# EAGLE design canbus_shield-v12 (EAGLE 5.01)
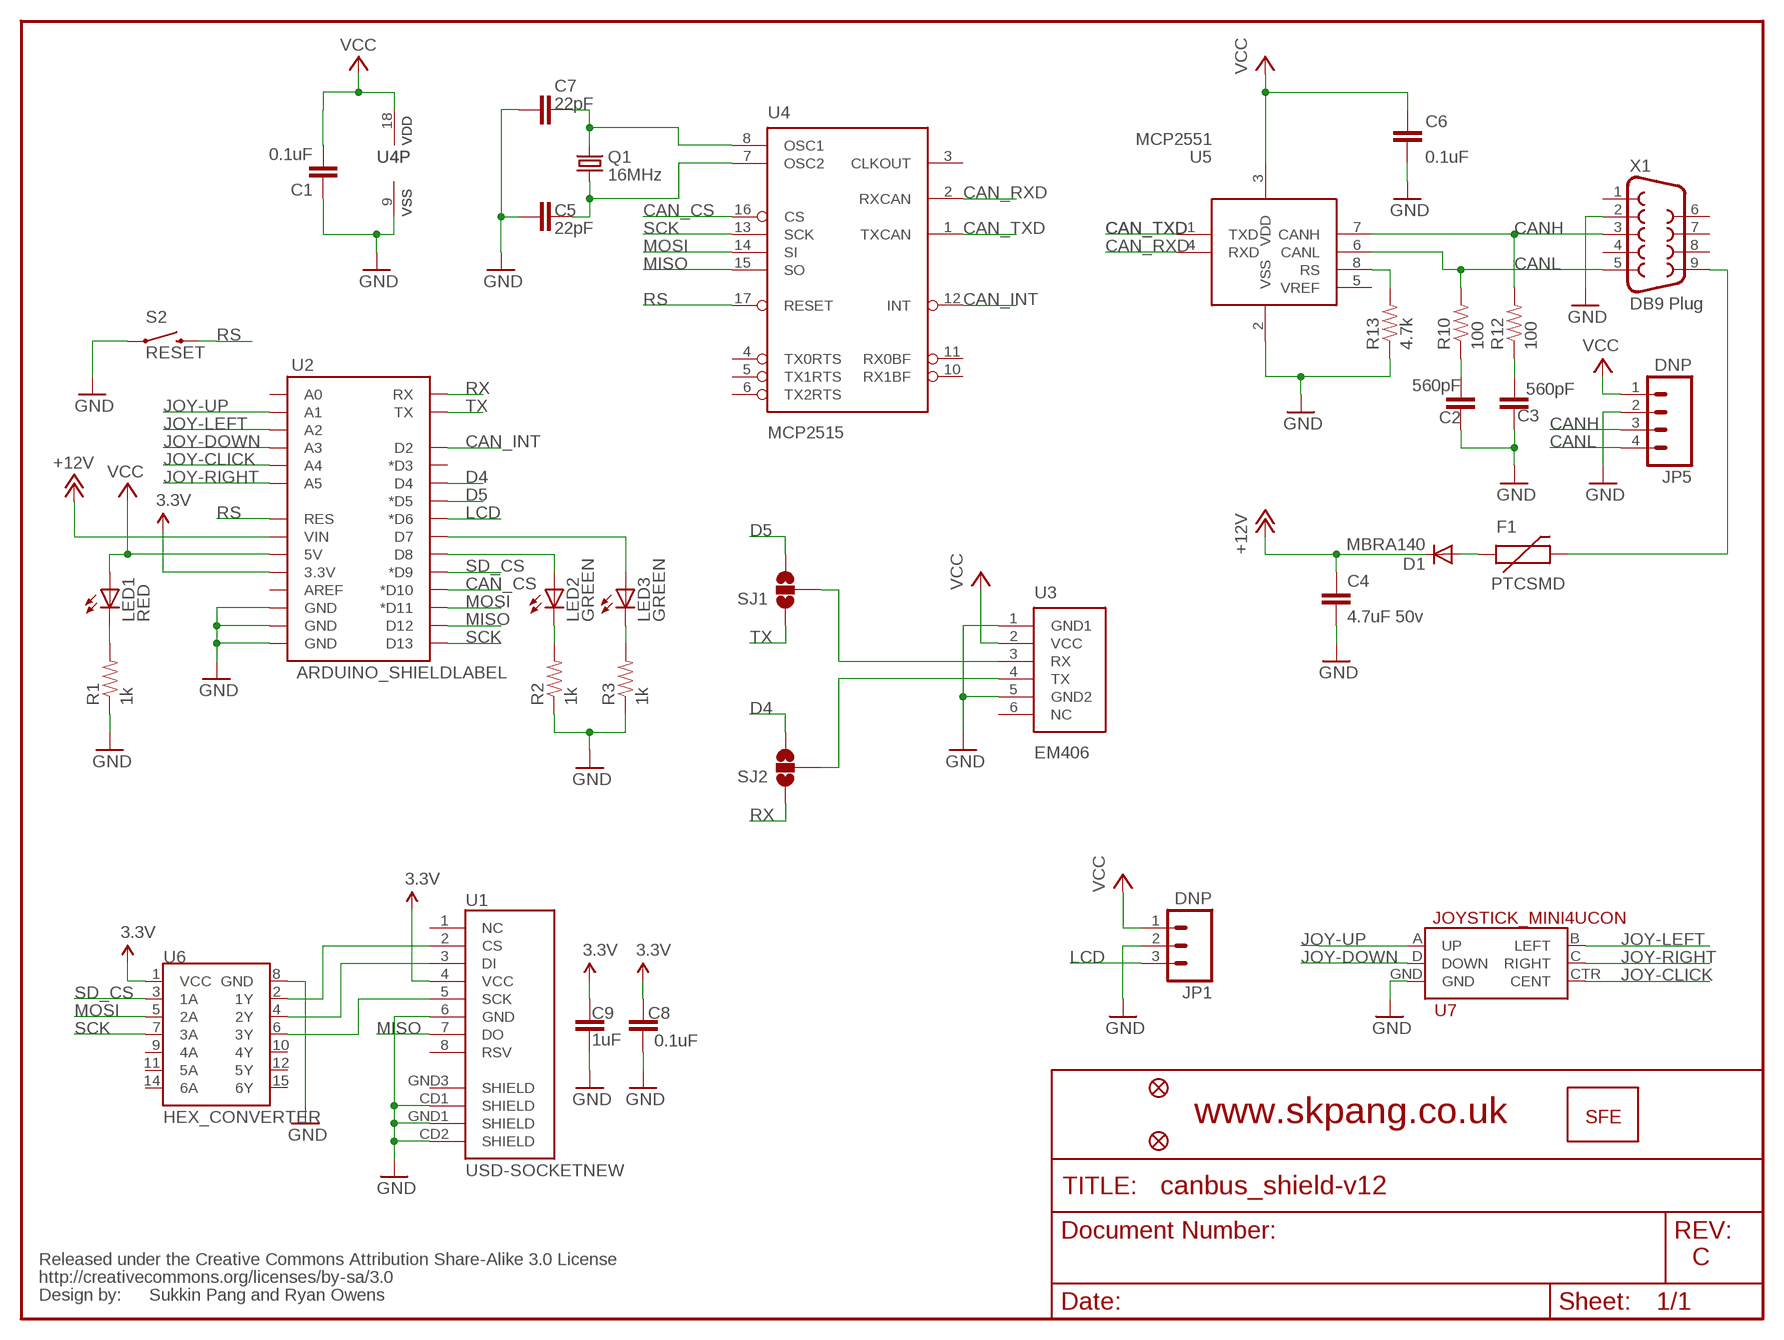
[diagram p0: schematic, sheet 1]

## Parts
C1  0.1uF  CAP0603-CAP  [0603-CAP]
C2  560pF  CAP0603-CAP  [0603-CAP]
C3  560pF  CAP0603-CAP  [0603-CAP]
C4  4.7uF 50v  CAP0603-CAP  [0603-CAP]
C5  22pF  CAP0603-CAP  [0603-CAP]
C6  0.1uF  CAP0603-CAP  [0603-CAP]
C7  22pF  CAP0603-CAP  [0603-CAP]
C8  0.1uF  CAP0603-CAP  [0603-CAP]
C9  1uF  CAP0603-CAP  [0603-CAP]
D1  MBRA140  DIODESMA  [SMA-DIODE]
F1  PTCSMD  [PTC-1206]
JP1  DNP  M03POLAR_LOCK  [MOLEX-1X3_LOCK]
JP2  FIDUCIAL1X2  [FIDUCIAL-1X2]
JP3  FIDUCIAL1X2  [FIDUCIAL-1X2]
JP4  LOGO-SFENEW  [SFE-NEW-WEBLOGO]
JP5  DNP  M04PTH  [1X04]
LED1  RED  LED0603  [LED-0603]
LED2  GREEN  LED0603  [LED-0603]
LED3  GREEN  LED0603  [LED-0603]
Q1  16MHz  CRYSTAL5X3  [CRYSTAL-SMD-5X3]
R1  1k  RESISTOR0603-RES  [0603-RES]
R2  1k  RESISTOR0603-RES  [0603-RES]
R3  1k  RESISTOR0603-RES  [0603-RES]
R10  100  RESISTOR0603-RES  [0603-RES]
R12  100  RESISTOR0603-RES  [0603-RES]
R13  4.7k  RESISTOR0603-RES  [0603-RES]
S2  RESET  SWITCH-MOMENTARY-2SMD  [TACTILE_SWITCH_SMD]
SJ1  SOLDERJUMPER_2WAYPASTE2&3  [SJ_3_PASTE2&3]
SJ2  SOLDERJUMPER_2WAYPASTE2&3  [SJ_3_PASTE2&3]
U1  USD-SOCKETNEW  [MICRO-SD-SOCKET-PP]
U2  ARDUINO_SHIELDLABEL  [DUEMILANOVE_SHIELD]
U3  EM406  [EM406]
U4  MCP2515  MCP2510SO  [SO-18W]
U5  MCP2551  [SO-08M]
U6  HEX_CONVERTER  [SO016]
U7  JOYSTICK_MINI4UCON  [JOYSTICK_MINI]
U$1  CREATIVE_COMMONS  [CREATIVE_COMMONS]
X1  DB9 Plug  DB9MALE  [DB9_MALE]

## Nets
3.3V: C8.2 C9.1 U1.4(VCC) U2.3.3V U6.1(VCC)
+12V: C4.1 D1.C U2.VIN
CAN_CS: U2.D10(*D10) U4.16(CS)
CAN_INT: U2.D2 U4.12(INT)
CAN_RXD: U4.2(RXCAN) U5.4(RXD)
CAN_TXD: U4.1(TXCAN) U5.1(TXD)
CANH: JP5.3 R12.2 U5.7(CANH) X1.3
CANL: JP5.4 R10.2 U5.6(CANL) X1.5
D4: SJ2.3 U2.D4
D5: SJ1.3 U2.D5(*D5)
GND: C1.1 C2.1 C3.1 C4.2 C5.1 C6.1 C7.1 C8.1 C9.2 JP1.2 JP5.2 R1.1 R2.1 R3.1 R13.1 S2.1 U1.6(GND) U1.CD1(SHIELD) U1.CD2(SHIELD) U1.GND1(SHIELD) U2.GND@0(GND) U2.GND@1(GND) U2.GND@2(GND) U3.1(GND1) U3.5(GND2) U4.9(VSS) U5.2(VSS) U6.8(GND) U7.GND X1.2
JOY-CLICK: U2.A4 U7.CTR(CENT)
JOY-DOWN: U2.A3 U7.D(DOWN)
JOY-LEFT: U2.A2 U7.B(LEFT)
JOY-RIGHT: U2.A5 U7.C(RIGHT)
JOY-UP: U2.A1 U7.A(UP)
LCD: JP1.3 U2.D6(*D6)
MISO: U1.7(DO) U2.D12 U4.15(SO)
MOSI: U2.D11(*D11) U4.14(SI) U6.5(2A)
N$4: LED1.C R1.2
N$5: LED2.C R2.2
N$6: LED3.C R3.2
N$9: C2.2 R10.1
N$10: C3.2 R12.1
N$11: LED2.A U2.D8
N$12: LED3.A U2.D7
N$13: F1.2 X1.9
N$14: R13.2 U5.8(RS)
N$15: U1.2(CS) U6.2(1Y)
N$16: D1.A F1.1
N$17: C7.2 Q1.3 U4.8(OSC1)
N$18: C5.2 Q1.1 U4.7(OSC2)
N$19: U1.3(DI) U6.4(2Y)
N$21: SJ1.2 U3.3(RX)
N$22: SJ2.2 U3.4(TX)
N$24: U1.5(SCK) U6.6(3Y)
RS: S2.3 U2.RES U4.17(RESET)
RX: SJ2.1 U2.RX
SCK: U2.D13 U4.13(SCK) U6.7(3A)
SD_CS: U2.D9(*D9) U6.3(1A)
TX: SJ1.1 U2.TX
VCC: C1.2 C6.2 JP1.1 JP5.1 LED1.A U2.5V U3.2(VCC) U4.18(VDD) U5.3(VDD)
Unconnected: U1.1(NC) U1.8(RSV) U1.GND3(SHIELD) U2.A0 U2.AREF U2.D3(*D3) U3.6(NC) U4.3(CLKOUT) U4.4(TX0RTS) U4.5(TX1RTS) U4.6(TX2RTS) U4.10(RX1BF) U4.11(RX0BF) U5.5(VREF) U6.9(4A) U6.10(4Y) U6.11(5A) U6.12(5Y) U6.14(6A) U6.15(6Y) X1.1 X1.4 X1.6 X1.7 X1.8

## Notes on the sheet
- www.skpang.co.uk
- C
- Sukkin Pang and Ryan Owens

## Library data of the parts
C1-C9 = SparkFun:CAP: Capacitor
D1 = SparkFun:DIODE: Diode
F1 = SparkFun:PTC: Resettable Fuse PTC
JP1 = SparkFun:M03: Header 3 Standard 3-pin 0.1" header. Use with straight break away headers (SKU : PRT-00116), right angle break away headers (PRT-00553), swiss pins (PRT-00743), machine pins (PRT-00117), and female headers (PRT-00115). Molex polarized connector foot print use with SKU : PRT-08232 with associated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
JP2 JP3 = SparkFun:FIDUCIAL: Fiducial Alignment Points
JP4 = SparkFun:LOGO-SFE: Spark Fun Electronics PCB Logo
JP5 = SparkFun:M04: Header 4 Standard 4-pin 0.1" header. Use with straight break away headers (SKU : PRT-00116), right angle break away headers (PRT-00553), swiss pins (PRT-00743), machine pins (PRT-00117), and female headers (PRT-00115). Molex polarized connector foot print use with SKU : PRT-08231 with associated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
LED1-LED3 = SparkFun:LED: LEDs
Q1 = SparkFun:CRYSTAL: Crystals
R1-R3 R10 R12 R13 = SparkFun:RESISTOR: Resistor
S2 = SparkFun:SWITCH-MOMENTARY-2
SJ1 SJ2 = SparkFun:SOLDERJUMPER_2WAY: Solder Jumper 2 way solder jumper
U1 = SparkFun:USD-SOCKET: microSD Socket Push-push type uSD socket. Schematic element and footprint production proven. Spark Fun Electronics SKU : PRT-00127. tDoc lines correctly indicate media card edge positions when inserting (unlocked, locked, depressed).
U2 = SparkFun:ARDUINO_SHIELD
U3 = SparkFun:EM406: EM406 Connector Proven layout and schematic for EM406 connector. Spark Fun Electronics SKU : GPS-00579
U4 = microchip_can:MCP2510
U5 = skpang_lib:MCP2551
U6 = SparkFun:HEX_CONVERTER
U7 = SparkFun:JOYSTICK_MINI
U$1 = SparkFun:CREATIVE_COMMONS
X1 = SparkFun:DB9: DB9 Connector Standard DB9 (D-Sub 9) serial connector. Can be used for CAN bus as well as RS485 and RS232. Footprint production proven. Spark Fun Electronics SKU : PRT-00429

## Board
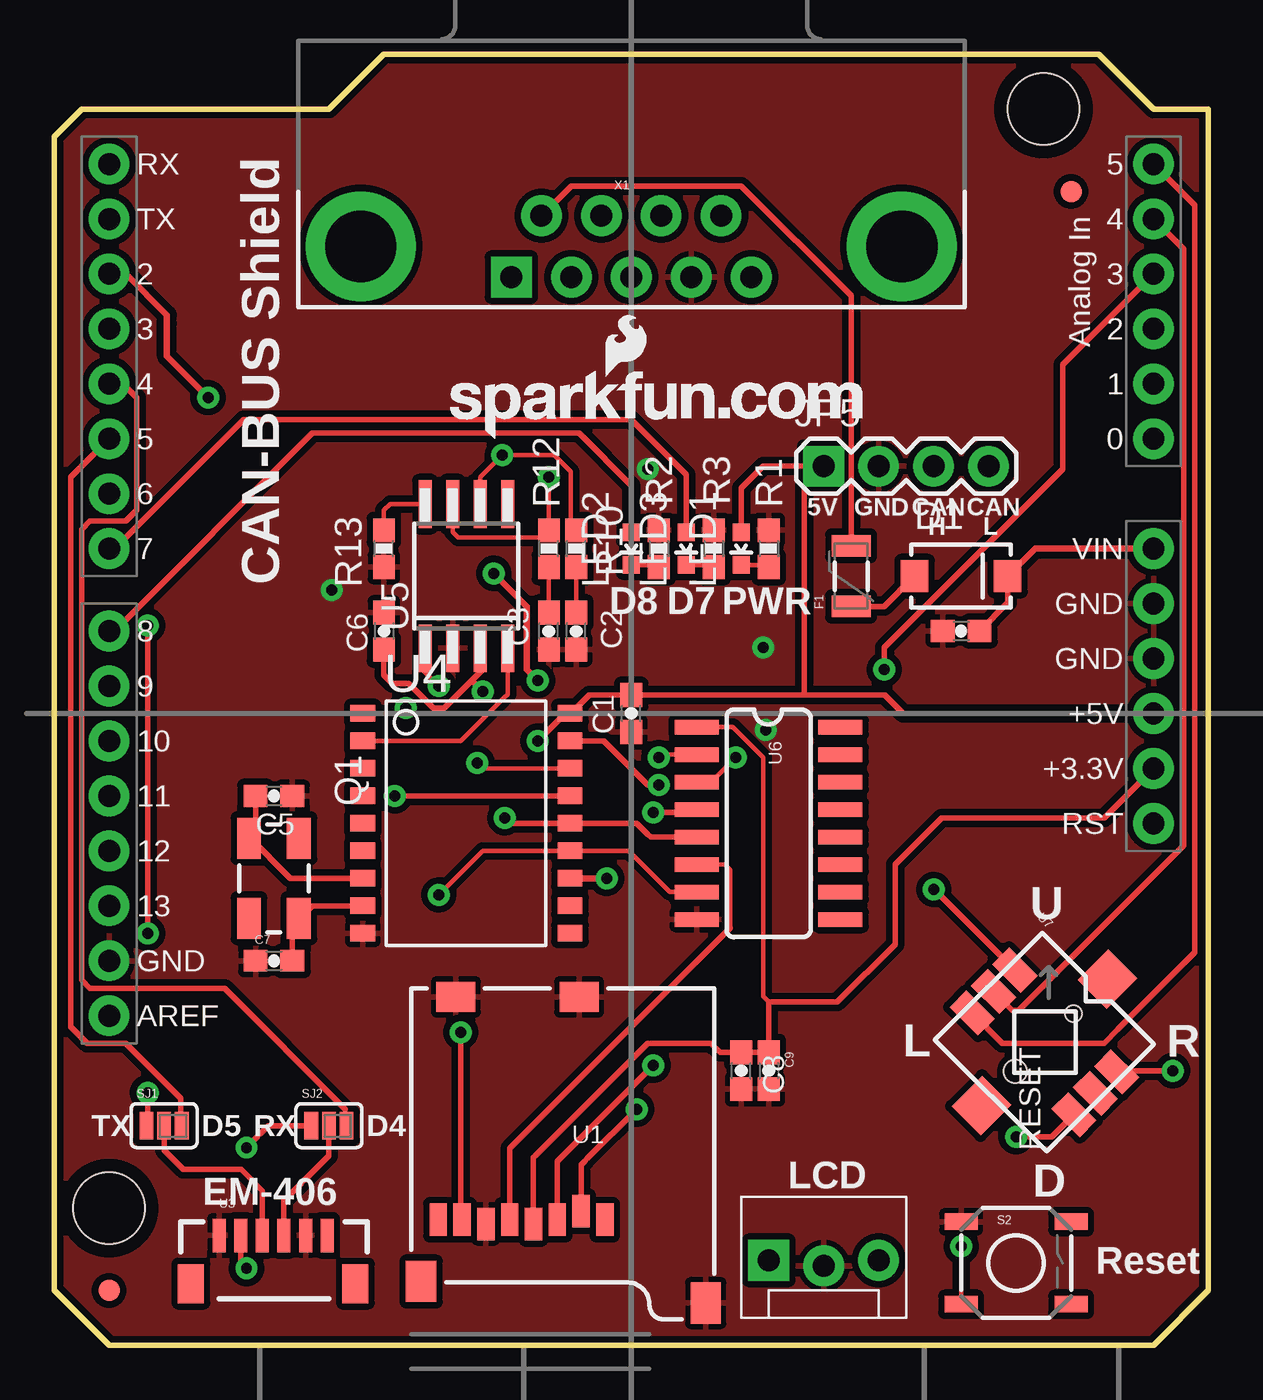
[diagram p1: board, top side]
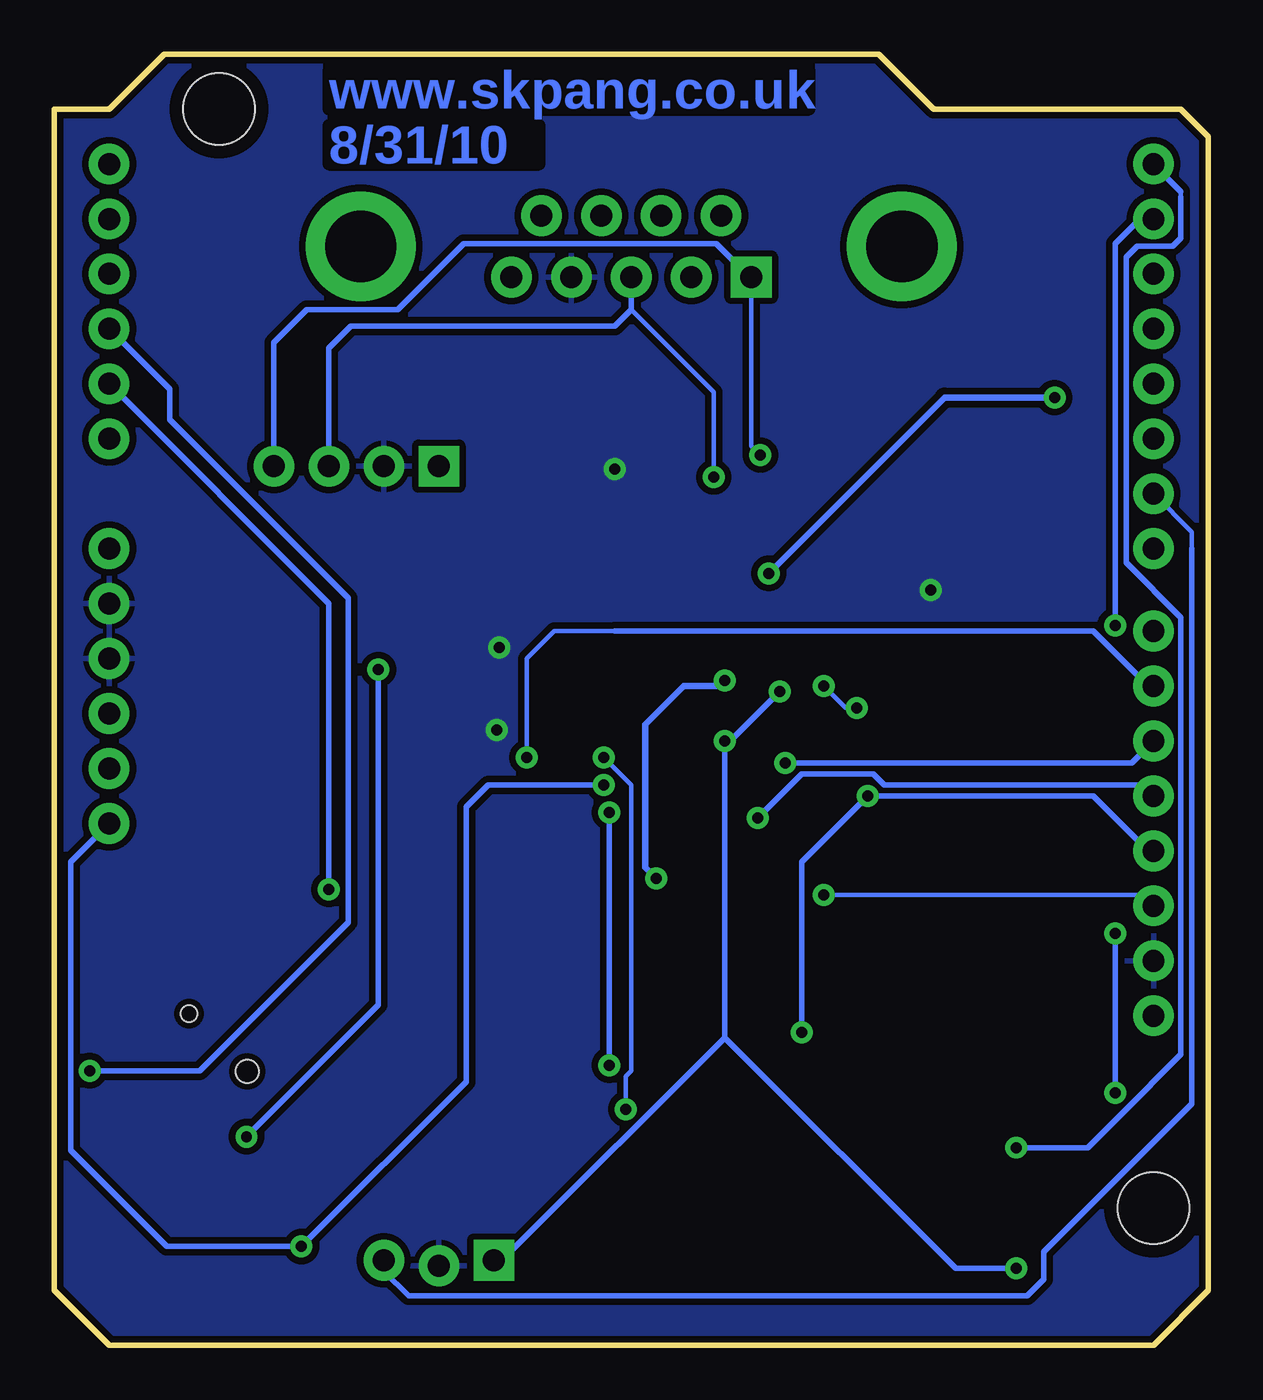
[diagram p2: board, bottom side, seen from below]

Size 53.34 x 59.69 mm. Coordinates in mm from the lower left corner, seen from the top.
Outline: 0,2.54 0,55.88 1.27,57.15 12.7,57.15 15.24,59.69 48.26,59.69 50.8,57.15 53.34,57.15 53.34,2.54 50.8,0 2.54,0 0,2.54
Copper layers (1*16): Top 0.035mm / dielectric 1.5mm / Bottom 0.035mm
Design rules "SparkFun": minimum track width 8mil, minimum drill 20mil, track to track 8mil, track to pad 8mil, pad to pad 8mil, via to via 8mil, smd to smd 8mil, copper to edge 8mil, drill to drill 8mil, minimum pad ring 12mil, minimum via ring 10mil, stop-mask expansion 4mil, vias tented up to drill 20mil, thermal gap 10mil

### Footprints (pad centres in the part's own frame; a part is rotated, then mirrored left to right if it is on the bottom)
0603-CAP = smd 1.1 x 1: 1 -0.85,0; 2 0.85,0
SMA-DIODE = smd 1.27 x 1.47: A -2.15,0; C 2.15,0
PTC-1206 = smd 1 x 1.8: 1 -1.4,0; 2 1.4,0
MOLEX-1X3_LOCK = drill 1.016 pad 1.88 square: 1 0,0.127 | drill 1.016 pad 1.88 round: 2 2.54,-0.127; 3 5.08,0.127
FIDUCIAL-1X2 = smd 1 x 1: 1 0,0
1X04 = drill 1.016 pad 1.88 square: 1 0,0 | drill 1.016 pad 1.88 round: 2 2.54,0; 3 5.08,0; 4 7.62,0
LED-0603 = smd 0.8 x 0.8: A 0,-0.75; C 0,0.75
CRYSTAL-SMD-5X3 = smd 1.9 x 1.1: 1 -1.85,-1.15; 2 1.85,-1.15; 3 1.85,1.15; 4 -1.85,1.15
0603-RES = smd 1.1 x 1: 1 -0.85,0; 2 0.85,0
TACTILE_SWITCH_SMD = smd 1.524 x 0.762: 1 -2.54,1.905; 2 2.54,1.905; 3 -2.54,-1.905; 4 2.54,-1.905
SJ_3_PASTE2&3 = smd 0.635 x 1.27: 1 -0.813,0; 2 0,0; 3 0.813,0
MICRO-SD-SOCKET-PP = smd 0.8 x 1.5: 1 -8.94,10.7; 2 -7.84,10.3; 3 -6.74,10.7; 4 -5.64,10.9; 5 -4.54,10.7; 6 -3.44,10.9; 7 -2.34,10.7; 8 -1.24,10.7 | smd 1.8 x 1.4: CD1 -2.05,0.4; CD2 -7.75,0.4 | smd 1.4 x 1.9: GND1 -13.6,14.55; GND3 -0.45,13.55
DUEMILANOVE_SHIELD = drill 1.016 pad 1.88 round: 3.3V 50.8,26.67; 5V 50.8,29.21; A0 50.8,41.91; A1 50.8,44.45; A2 50.8,46.99; A3 50.8,49.53; A4 50.8,52.07; A5 50.8,54.61; AREF 2.54,15.24; D2 2.54,49.53; D3 2.54,46.99; D4 2.54,44.45; D5 2.54,41.91; D6 2.54,39.37; D7 2.54,36.83; D8 2.54,33.02; D9 2.54,30.48; D10 2.54,27.94; D11 2.54,25.4; D12 2.54,22.86; D13 2.54,20.32; GND@0 50.8,31.75; GND@1 50.8,34.29; GND@2 2.54,17.78; RES 50.8,24.13; RX 2.54,54.61; TX 2.54,52.07; VIN 50.8,36.83 | hole 3.302: 45.72,57.15; 2.54,6.35
EM406 = smd 0.6 x 1.55: 1 0,0; 2 1,0; 3 2,0; 4 3,0; 5 4,0; 6 5,0 | smd 1.2 x 1.8: P$1 -1.3,-2.225; P$2 6.3,-2.225
SO-18W = smd 0.762 x 1.143: 1 -5.08,-4.788; 2 -3.81,-4.788; 3 -2.54,-4.788; 4 -1.27,-4.788; 5 0,-4.788; 6 1.27,-4.788; 7 2.54,-4.788; 8 3.81,-4.788; 9 5.08,-4.788; 10 5.08,4.788; 11 3.81,4.788; 12 2.54,4.788; 13 1.27,4.788; 14 0,4.788; 15 -1.27,4.788; 16 -2.54,4.788; 17 -3.81,4.788; 18 -5.08,4.788
SO-08M = smd 0.6 x 2.2: 1 -1.905,-3.33; 2 -0.635,-3.33; 3 0.635,-3.33; 4 1.905,-3.33; 5 1.905,3.33; 6 0.635,3.33; 7 -0.635,3.33; 8 -1.905,3.33
SO016 = smd 0.66 x 2.032: 1 -4.445,-3.315; 2 -3.175,-3.315; 3 -1.905,-3.315; 4 -0.635,-3.315; 5 0.635,-3.315; 6 1.905,-3.315; 7 3.175,-3.315; 8 4.445,-3.315; 9 4.445,3.315; 10 3.175,3.315; 11 1.905,3.315; 12 0.635,3.315; 13 -0.635,3.315; 14 -1.905,3.315; 15 -3.175,3.315; 16 -4.445,3.315
JOYSTICK_MINI = smd 1.85 x 1.1: A 0,2.8; B 6.65,2.8; C 0,0; CTR 0,1.4; D 6.65,0; GND 6.65,1.4 | smd 1.9 x 2: NC 3.325,5.53; NC@0 3.33,-2.72 | hole 0.75: 3.34,3.295 | hole 1.05: 3.325,-0.5
DB9_MALE = drill 1.016 pad 1.88 round: 1 5.54,-1.42; 2 2.77,-1.42; 3 0,-1.42; 4 -2.77,-1.42; 6 4.15,1.42; 7 1.38,1.42; 8 -1.38,1.42; 9 -4.15,1.42 | drill 1.016 pad 1.88 square: 5 -5.54,-1.42 | drill 3.302 pad 5.08 round: G1 -12.5,0; G2 12.5,0

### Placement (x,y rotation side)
C1  26.67,29.21 90 top
C2  24.13,33.02 90 top
C3  22.86,33.02 90 top
C4  41.91,33.02 180 top
C5  10.16,25.4 180 top
C6  15.24,33.02 270 top
C7  10.16,17.78 0 top
C8  31.75,12.7 90 top
C9  33.02,12.7 270 top
D1  41.91,35.56 0 top
F1  36.83,35.56 90 top
JP1  33.02,3.81 0 top
JP2  2.54,2.54 0 top
JP3  46.99,53.34 0 top
JP4  18.29,41.91 0 top
JP5  35.56,40.64 0 top
LED1  31.75,36.83 180 top
LED2  26.67,36.83 180 top
LED3  29.21,36.83 180 top
Q1  10.16,21.59 270 top
R1  33.02,36.83 270 top
R2  27.94,36.83 270 top
R3  30.48,36.83 270 top
R10  24.13,36.83 90 top
R12  22.86,36.83 90 top
R13  15.24,36.83 90 top
S2  44.45,3.81 0 top
SJ1  5.08,10.16 0 top
SJ2  12.7,10.16 0 top
U1  16.51,16.51 180 top
U2  0,0 0 top
U3  7.62,5.08 0 top
U4  19.05,24.13 270 top
U5  19.05,35.56 0 top
U6  33.02,24.13 270 top
U7  42.42,15.37 315 top
U$1  not placed on the board
X1  26.67,50.8 0 top

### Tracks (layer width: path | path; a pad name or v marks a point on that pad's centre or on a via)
3.3V
  Top 0.203: U6.1 31.37,28.57 31.5,28.45 32.77,27.18 32.77,16.13 33.02,15.88 | 27.43,13.97 27.56,13.97 | C9.1 33.02,13.46 32.93,13.55
  Top 0.254: 27.43,13.97 22.35,8.89 22.23,8.76 22.15,8.69 U1.4 | 27.56,13.97 30.35,13.97 30.77,13.55 C8.2 32.93,13.55 | C9.1 33.02,15.88 36.2,15.88 38.86,18.54 38.86,22.23 41.02,24.38 48.51,24.38 U2.3.3V
+12V
  Top 0.254: D1.C 44.07,35.43 44.07,34.33 C4.1
  Top 0.305: U2.VIN 50.04,36.83 46.48,36.83 46.35,36.83 46.1,36.83 45.33,36.83 D1.C
CAN_CS  (via drill 0.51)
  Top 0.203: v19.56,26.92 19.68,26.92 19.94,26.67 U4.16
  Bottom 0.203: 3.68,26.92 3.81,26.92
  Bottom 0.254: 3.81,26.92 v19.56,26.92 | U2.D10 3.56,26.92 3.68,26.92
CAN_INT  (via drill 0.51)
  Top 0.305: U4.12 v25.53,21.59 | v22.35,30.73 21.84,31.24 21.84,31.75 21.84,34.16 v20.32,35.69 | v7.11,43.81 5.21,45.72 5.21,47.24 5.21,47.62 3.3,49.53 U2.D2
  Bottom 0.305: v22.35,30.73 22.61,30.48 24.26,30.48 26.04,28.7 26.04,26.04 26.04,22.1 v25.53,21.59 | v20.32,35.69 12.19,43.81 v7.11,43.81
CAN_RXD
  Top 0.203: U4.2 18.8,27.94 18.92,28.07 19.05,28.19 20.83,29.97 20.95,30.1 U5.4
CAN_TXD  (via drill 0.51)
  Top 0.203: v17.78,30.48 17.02,31.24 U5.1 | U4.1 16,29.21 v16.26,29.46
  Bottom 0.203: v16.26,29.46 16.76,29.46 v17.78,30.48
CANH  (via drill 0.51)
  Top 0.203: v22.86,40.13 22.86,38.1 R12.2 22.61,37.34 19.05,37.34 18.67,37.34 18.41,37.59 U5.7
  Bottom 0.203: v22.86,40.13 22.86,44.07 26.67,47.88
  Bottom 0.254: X1.3 26.67,47.88 27.43,47.12 39.62,47.12 40.64,46.1 JP5.3
CANL  (via drill 0.51)
  Top 0.203: R10.2 23.88,38.1 23.88,40.39 23.11,41.15 21.08,41.15 v20.7,41.15 19.68,40.13 U5.6
  Bottom 0.203: X1.5 21.13,41.58 v20.7,41.15
  Bottom 0.254: 21.08,49.28 21.13,49.32 X1.5 21.19,49.38 21.21,49.4 22.73,50.93 34.42,50.93 37.47,47.88 41.66,47.88 43.18,46.35 JP5.4
D4
  Top 0.203: 13.46,10.92 13.46,10.67 SJ2.3 | 3.81,42.93 3.81,43.05
  Top 0.254: 13.46,10.92 7.87,16.51 2.03,16.51 1.65,16.51 1.27,16.89 1.27,17.27 1.27,37.34 1.27,37.72 1.65,38.1 2.03,38.1 3.05,38.1 3.3,38.1 3.81,38.61 3.81,38.86 3.81,42.93 | U2.D4 3.17,44.45 3.81,43.81 3.81,43.05
D5
  Top 0.203: 5.84,10.67 SJ1.3
  Top 0.254: 5.84,10.67 5.84,11.43 3.3,13.97 2.03,13.97 1.52,13.97 0.76,14.73 0.76,15.24 0.76,39.88 0.76,40.01 0.76,40.13 U2.D5
GND  (via drill 0.51)
  other vias: 32.89,28.45 27.43,40.51 32.77,32.26 12.83,34.92
  pour Bottom (isolate 0.305): 0,0 0,59.69 53.34,59.69 53.34,0
  pour Top (isolate 0.305): 0,0 0,59.69 53.34,59.69 53.34,0
JOY-CLICK
  Top 0.254: U2.A4 52.2,50.67 52.2,49.78 52.2,24 52.2,23.75 52.2,23.11 44.58,15.49 44.27,15.49 U7.CTR
JOY-DOWN  (via drill 0.51)
  Top 0.254: U2.A3 46.61,45.34 46.61,40.51 38.35,32.26 38.35,31.75 v38.35,31.24 | U7.D 46.11,9.65 v44.45,9.65
  Bottom 0.254: v38.35,31.24 38.35,27.05 38.35,15.75 v44.45,9.65
JOY-LEFT  (via drill 0.51)
  Top 0.254: U7.B 49.16,12.7 v51.69,12.7
  Bottom 0.254: U2.A2 48.01,44.2 48.01,42.93 48.01,42.8 39.75,34.54 39.75,19.56 46.61,12.7 v51.69,12.7
JOY-RIGHT
  Top 0.254: U2.A5 52.7,52.7 52.7,23.5 52.7,21.75 52.7,18.16 49.15,14.61 48.51,13.97 45.72,13.97 45.47,13.97 43.81,13.97 U7.C
JOY-UP  (via drill 0.51)
  Top 0.254: U7.A 40.64,21.11 v40.64,21.08
  Bottom 0.254: v40.64,21.08 40.64,27.94 40.64,34.04 40.64,34.29 U2.A1
LCD
  Bottom 0.203: 0.76,36.83 0.76,36.96 0.76,37.59 U2.D6
  Bottom 0.254: 0.76,36.83 0.76,11.18 7.62,4.32 7.62,3.05 8.38,2.29 36.07,2.29 36.32,2.29 36.96,2.29 38.1,3.43 JP1.3
MISO  (via drill 0.51)
  Top 0.203: 23.37,25.4 U4.15 | U1.7 18.8,6.35
  Top 0.254: v15.75,25.4 23.37,25.4 | 18.8,6.35 v18.8,14.48
  Bottom 0.203: 3.3,23.37 U2.D12
  Bottom 0.254: 3.3,23.37 5.33,25.4 v15.75,25.4 16,25.15 18.8,22.35 v18.8,14.48
MOSI  (via drill 0.51)
  Top 0.254: v20.83,24.38 21.08,24.13 U4.14 26.92,24.13 27.18,23.88 27.43,23.62 27.56,23.5 U6.5
  Bottom 0.254: v20.83,24.38 18.8,26.42 15.49,26.42 14.99,25.91 3.3,25.91 U2.D11
N$4
  Top 0.203: LED1.C 32,36.07 32.77,36.07 R1.2
N$5
  Top 0.203: LED2.C 26.92,36.07 27.69,36.07 R2.2
N$6
  Top 0.203: LED3.C 29.46,36.07 30.23,36.07 R3.2
N$9
  Top 0.203: C2.2 24.13,34.29 24.13,35.56 R10.1
N$10
  Top 0.203: C3.2 22.86,34.29 22.86,35.56 R12.1
N$11
  Top 0.203: LED2.A 26.42,37.34
  Top 0.254: U2.D8 2.79,33.02 3.17,33.4 3.3,33.53 11.43,41.66 11.94,42.16 20.07,42.16 24.26,42.16 26.67,39.75 26.67,39.62 LED2.A
N$12
  Top 0.203: LED3.A 28.96,37.34
  Top 0.254: U2.D7 3.3,37.34 8.76,42.8 13.46,42.8 13.59,42.8 26.67,42.8 29.21,40.26 LED3.A
N$13
  Top 0.254: X1.9 23.89,53.59 24.64,53.59 31.24,53.59 31.75,53.59 36.83,48.51 36.83,48.01 36.83,47.12 F1.2
N$14
  Top 0.203: U5.8 15.52,38.89 15.24,38.61 15.24,38.48 R13.2
N$15  (via drill 0.51)
  Top 0.203: U6.2 28.07,27.3 v27.94,27.18
  Top 0.254: v26.92,10.92 24.64,8.64 24.51,8.51 24.35,8.35 U1.2
  Bottom 0.203: v26.92,10.92 26.92,12.45 26.67,12.7 26.67,25.91 v27.94,27.18
N$16
  Top 0.254: D1.A 38.35,34.16 F1.1
N$17
  Top 0.254: U4.8 11.94,20.32 11.3,19.68 11.31,19.69 Q1.3 11.31,19.8 11.3,19.81 11.01,19.52 C7.2
N$18
  Top 0.254: U4.7 10.92,21.59 9.02,23.5 9.01,23.49 Q1.1 9.01,23.38 9.02,23.37 9.31,23.66 C5.2
N$19  (via drill 0.51)
  Top 0.203: 28.7,24.64 U6.4
  Top 0.254: v27.69,12.95 23.62,8.89 23.5,8.76 23.25,8.52 U1.3 | v27.69,24.64 28.7,24.64
  Bottom 0.254: v27.69,12.95 v27.69,24.64
N$21
  Top 0.254: SJ1.2 5.08,9.02 5.97,8.13 6.22,8.13 8.64,8.13 9.62,7.14 U3.3
N$22
  Top 0.203: 11.43,7.49 11.56,7.62
  Top 0.254: U3.4 10.62,6.68 11.43,7.49 | SJ2.2 12.7,8.76 11.56,7.62
N$24
  Top 0.203: 31.24,19.3 31.24,21.34 31.24,21.59 31.24,21.97 30.99,22.23 U6.6
  Top 0.254: 31.24,19.3 21.34,9.4 21.21,9.27 21.05,9.11 U1.5
RS  (via drill 0.51)
  Top 0.203: v41.91,4.57 41.91,2.03 S2.3
  Top 0.254: v27.94,25.91 27.43,25.91 25.65,27.69 25.4,27.94 U4.17
  Bottom 0.254: v27.94,25.91 33.27,25.91 34.29,24.89 34.29,12.19 v41.91,4.57 42.04,4.57 48.13,4.57 52.58,9.02 52.58,12.19 52.58,22.35 U2.RES
RX  (via drill 0.51)
  Top 0.203: 9.4,9.65 9.53,9.78
  Top 0.254: v8.89,9.14 9.4,9.65 | SJ2.1 9.91,10.16 9.53,9.78
  Bottom 0.203: 1.27,53.09 1.27,53.21 1.27,53.34
  Bottom 0.254: v8.89,9.14 6.6,9.14 6.48,9.14 5.59,9.14 4.06,10.67 1.27,13.46 1.27,33.53 1.27,33.66 3.81,36.2 3.81,36.32 3.81,50.04 3.81,50.29 3.3,50.8 3.05,50.8 2.03,50.8 1.65,50.8 1.27,51.18 1.27,51.56 1.27,53.09 | 1.27,53.34 U2.RX
SCK  (via drill 0.51)
  Top 0.203: U6.7 28.45,20.95 26.54,22.86 26.29,22.86 24.38,22.86 U4.13 19.81,22.86 v17.78,20.83
  Bottom 0.203: v17.78,20.83 3.3,20.83 U2.D13
SD_CS  (via drill 0.51)
  Top 0.203: v31.5,27.18 30.48,26.16 U6.3
  Bottom 0.203: v31.5,27.18 31.5,28.96 31.5,29.21 31.5,31.75 30.23,33.02 27.43,33.02 | U2.D9 3.3,30.99
  Bottom 0.254: 27.43,33.02 5.33,33.02 3.3,30.99
TX  (via drill 0.51)
  Top 0.203: SJ1.1 4.32,10.67
  Top 0.254: 4.32,10.67 v4.32,11.68 | v4.32,19.05 v4.32,33.27
  Bottom 0.254: v4.32,11.68 v4.32,19.05 | v4.32,33.27 4.32,50.55 4.32,50.93 3.17,52.07 U2.TX
VCC  (via drill 0.51)
  Top 0.203: 23.37,28.96 U4.18
  Top 0.254: 19.3,30.73 19.81,31.24 U5.3 | 19.3,30.73 18.03,29.46 17.53,29.46 16.76,30.23 16.64,30.35 16.38,30.61 15.62,30.61 15.24,30.99 C6.2 | v22.35,27.94 23.37,28.96 | v19.81,30.23 19.3,30.73 | U4.18 23.88,29.21 24.73,30.06 C1.2 27.56,30.06 27.73,30.06 29.04,30.06 34.67,30.06 | U2.5V 46.74,29.21 39.24,29.21 38.48,29.97 38.39,30.06 38.27,30.06 34.67,30.06 | U3.2 8.62,3.83 v8.89,3.56 | 34.67,30.06 34.67,30.1 34.67,39.75 JP5.1 32.77,40.64 31.75,39.62 LED1.A
  Bottom 0.203: 22.1,27.94 v22.35,27.94 22.61,28.19
  Bottom 0.254: 22.35,14.22 v22.35,27.94 | 22.35,14.22 32.26,4.32 32.38,4.19 32.64,3.94 JP1.1 | v8.89,3.56 11.68,3.56 22.35,14.22 | 22.1,27.94 v19.81,30.23

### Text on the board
Bottom: www.skpang.co.uk | 8/31/10
tPlace: 5V | GND | CAN | CAN | H | L | CAN-BUS Shield | D8 | D7 | PWR | U | L | R | TX | D5 | RX | D4 | LCD | D | EM-406 | Reset
tNames: RESET
tValues: Sukking Pang and Ryan Owens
